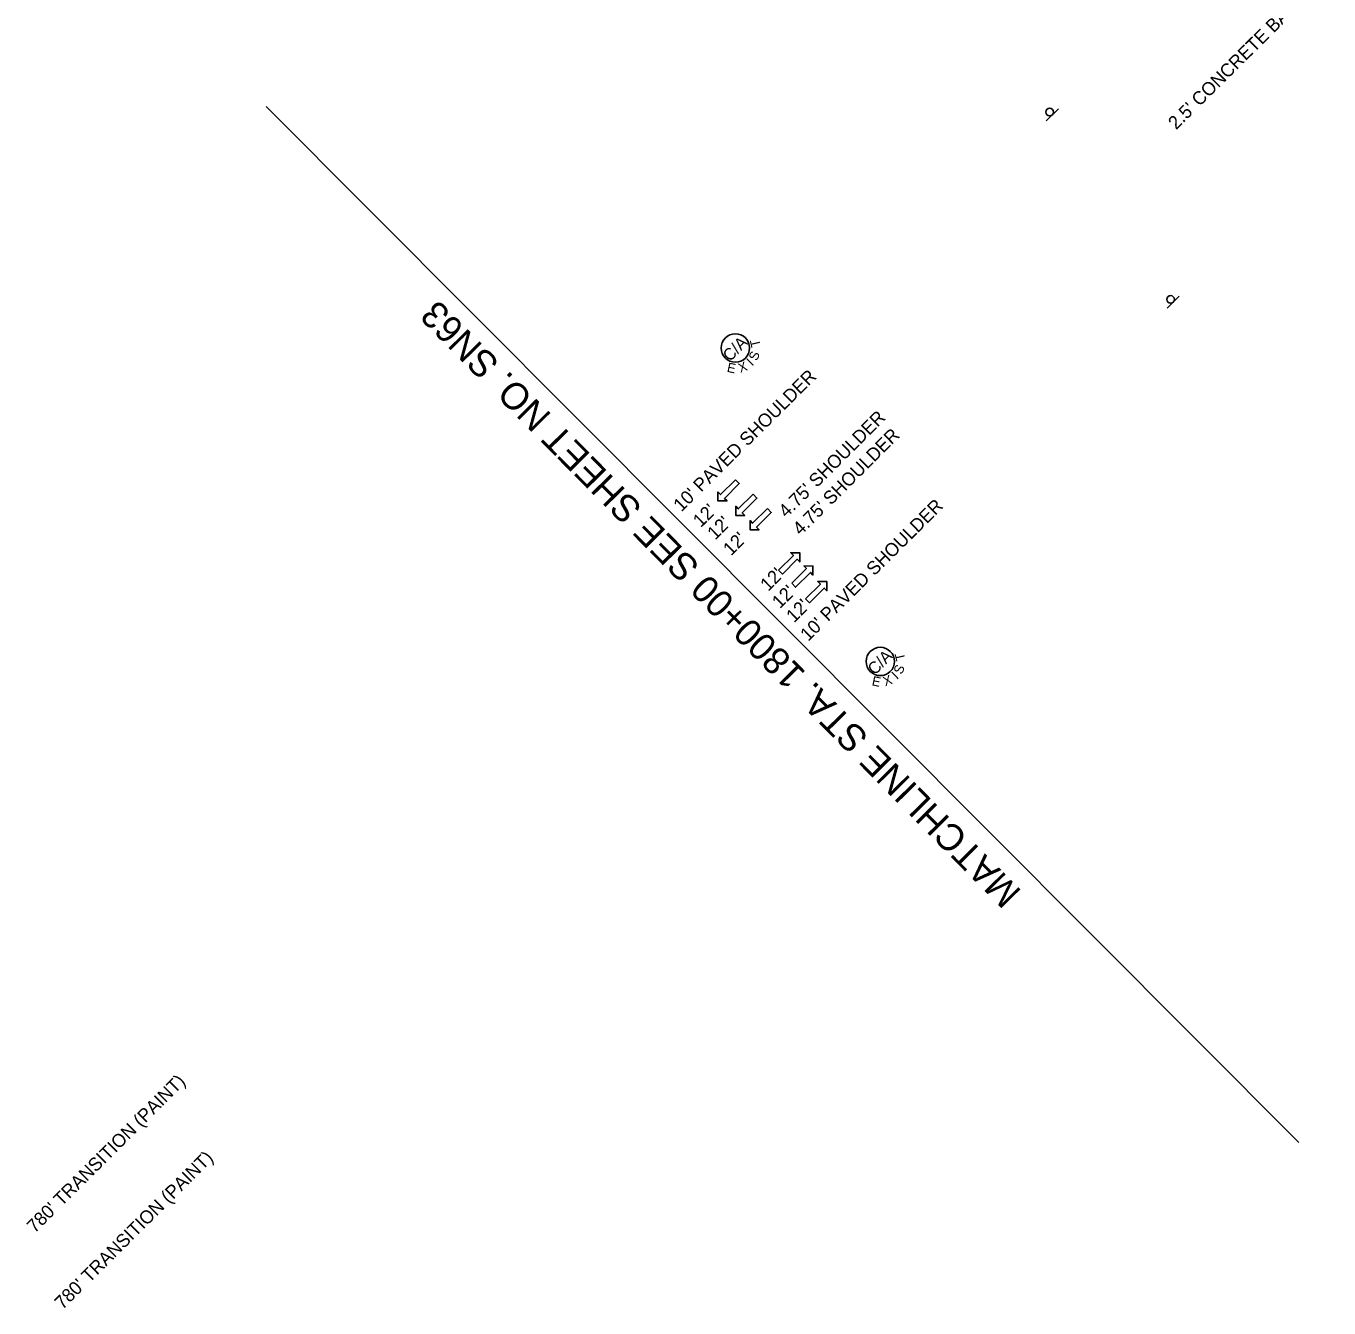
# Model space of a CAD drawing. Extents: x 1825735 to 1827318, y 1193725 to 1195507.
# Drawn here: x 1825735 to 1826424, y 1193725 to 1194402 of the extents above; entities that cross this region are included whole.
import ezdxf

# ---------------------------------------------------------------- set-up
doc = ezdxf.new("R2010")
doc.units = 0
for name, color, linetype in [('RD_HC_TX_Sta50', 7, 'Continuous'), ('RD_PD_Final_LnLine', 7, 'Continuous'), ('RD_PD_Final_TX', 7, 'Continuous'), ('RD_SHT_MatchLine', 7, 'Continuous'), ('RD_SHT_TX', 7, 'Continuous'), ('RD_Sketch8', 7, 'Continuous'), ('SN_P_Signs', 7, 'Continuous')]:
    doc.layers.add(name, color=color, linetype=linetype)

# ---------------------------------------------------------------- blocks, each defined once
blk = doc.blocks.new('SARRW2')
at = {"layer": 'RD_PD_Final_LnLine'}
blk.add_lwpolyline([(-12, 1.2), (-12, -1.2), (-2.83, -1.2), (-2.83, -2.83), (0, 0), (-2.83, 2.83), (-2.83, 1.2)], close=True, dxfattribs=at)

msp = doc.modelspace()

# ---------------------------------------------------------------- linework, layer by layer
at = {"layer": 'RD_SHT_MatchLine'}
msp.add_line((1825862.31, 1194359.18), (1826407.67, 1193812.08), dxfattribs=at)
at = {"layer": 'RD_Sketch8'}
for centre in [(1826110.07, 1194231.68), (1826186.58, 1194066.15)]:
    msp.add_circle(centre, 7.5, dxfattribs=at)
at = {"layer": 'SN_P_Signs'}
for p, q in [((1826274.27, 1194351.61), (1826280.64, 1194357.98)), ((1826338.13, 1194252.69), (1826344.5, 1194259.06))]:
    msp.add_line(p, q, dxfattribs=at)
for centre in [(1826276.04, 1194356.24), (1826339.9, 1194257.32)]:
    msp.add_circle(centre, 2, dxfattribs=at)

# ---------------------------------------------------------------- block references
at = {"layer": 'RD_PD_Final_LnLine', "xscale": 1.2000000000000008}
for p, yscale, rotation in [((1826100.86, 1194150.89), -1.2000000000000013, -135.0673694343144), ((1826110.22, 1194143.3), -1.2000000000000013, -135.0673694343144), ((1826117.79, 1194135.71), -1.2000000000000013, -135.0673694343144), ((1826144.09, 1194123.51), 1.200000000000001, 44.88558225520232), ((1826151.03, 1194116.55), 1.200000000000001, 44.88558225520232), ((1826158.37, 1194108.29), 1.200000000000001, 44.88558225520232)]:
    msp.add_blockref('SARRW2', p, dxfattribs=dict(at, yscale=yscale, rotation=rotation))

# ---------------------------------------------------------------- texts
at = {"layer": 'RD_HC_TX_Sta50'}
for p in [(1825740.05, 1193763.96), (1825754.72, 1193723.61)]:
    msp.add_text("780' TRANSITION (PAINT)", height=7, rotation=44.90911, dxfattribs=at).set_placement(p)
at = {"layer": 'RD_PD_Final_TX'}
for s, rotation, p in [("2.5' CONCRETE BARRIER", 44.75998, (1826342.79, 1194346.61)), ("10' PAVED SHOULDER", 44.726, (1826081.49, 1194144.83)), ("4.75' SHOULDER", 44.90911, (1826137.04, 1194141.68)), ("4.75' SHOULDER", 44.90911, (1826144.51, 1194132.35)), ("12'", 44.726, (1826091.8, 1194136.54)), ("10' PAVED SHOULDER", 44.726, (1826148.5, 1194076.49)), ("12'", 44.726, (1826099.41, 1194129.98)), ("12'", 44.726, (1826107.74, 1194121.62)), ("12'", 44.726, (1826127.35, 1194102.81)), ("12'", 44.726, (1826133.57, 1194093.66)), ("12'", 44.726, (1826141.06, 1194086.22))]:
    msp.add_text(s, height=7, rotation=rotation, dxfattribs=at).set_placement(p)
at = {"layer": 'RD_SHT_TX'}
msp.add_text('MATCHLINE STA. 1800+00 SEE SHEET NO. SN63', height=14.1726, rotation=134.62781, dxfattribs=at).set_placement((1826261.68, 1193944.74))
at = {"layer": 'RD_Sketch8'}
for s, height, rotation, p in [('C/A', 6.25, 44.90911, (1826107.14, 1194224.13)), ('T', 5, 103.09425, (1826123.44, 1194232.71)), ('X', 5, 20.54972, (1826112.69, 1194218.51)), ('I', 5, 44.70972, (1826118.96, 1194221.83)), ('S', 5, 66.70155, (1826121.42, 1194224.53)), ('E', 5, 348.12035, (1826105.32, 1194219.14)), ('C/A', 6.25, 44.90911, (1826183.65, 1194058.6)), ('T', 5, 103.09425, (1826199.95, 1194067.18)), ('X', 5, 20.54972, (1826189.2, 1194052.98)), ('I', 5, 44.70972, (1826195.47, 1194056.3)), ('S', 5, 66.70155, (1826197.93, 1194059)), ('E', 5, 348.12035, (1826181.83, 1194053.61))]:
    msp.add_text(s, height=height, rotation=rotation, dxfattribs=at).set_placement(p)

doc.saveas('drawing.dxf')
